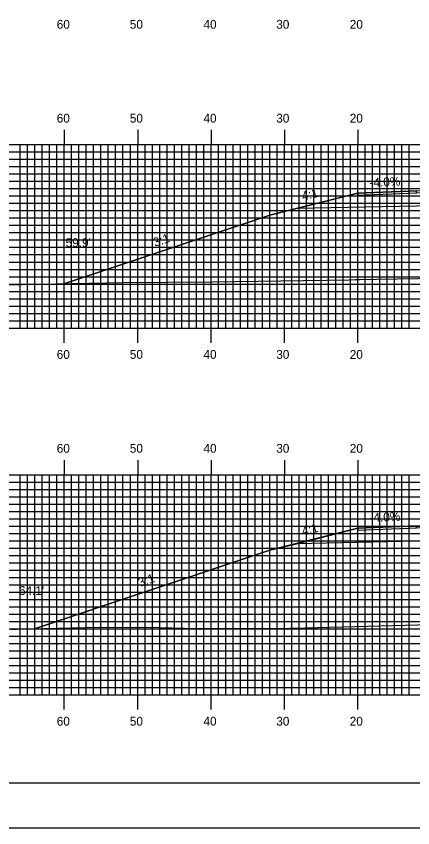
# Model space of a CAD drawing. Extents: x 1787763 to 1788106, y 442591 to 442811.
# Drawn here: x 1787862.1 to 1787916.1, y 442590.5 to 442701.2 of the extents above; entities that cross this region are included whole.
import ezdxf

# ---------------------------------------------------------------- set-up
doc = ezdxf.new("R2010")
doc.units = 0
for name, color, linetype in [('ANNOTATION', 7, 'Continuous'), ('BORDER', 7, 'Continuous'), ('D_Roadway_Centerline', 7, 'Continuous'), ('D_Roadway_Edge_Shoulder', 7, 'Continuous'), ('D_Roadway_SlopeLines', 7, 'Continuous'), ('D_Roadway_SubGrade', 7, 'Continuous'), ('D_Text_Standard', 7, 'Continuous'), ('H_V ANNOTATION', 7, 'Continuous'), ('MAJOR', 7, 'Continuous'), ('MINOR', 7, 'Continuous'), ('PLOT BOUNDARY', 7, 'Continuous'), ('S_Roadway_Centerline', 7, 'Continuous')]:
    doc.layers.add(name, color=color, linetype=linetype)

msp = doc.modelspace()

# ---------------------------------------------------------------- linework, layer by layer
at = {"layer": 'BORDER'}
msp.add_lwpolyline([(1787779.02, 442596.67), (1788099.02, 442596.67), (1788099.02, 442806.67), (1787779.02, 442806.67)], close=True, dxfattribs=at)
at = {"layer": 'D_Roadway_Centerline'}
for points in [[(1787868.67, 442664.72), (1787896.62, 442674.04), (1787900.25, 442674.95), (1787908.62, 442677.04), (1787916.62, 442677.36), (1787928.62, 442677.62), (1787940.62, 442677.89), (1787948.62, 442677.57), (1787956.98, 442675.48), (1787960.62, 442674.57), (1787989.3, 442665.01)], [(1787864.55, 442617.68), (1787896.62, 442628.37), (1787900.25, 442629.27), (1787908.62, 442631.37), (1787916.62, 442631.69), (1787928.62, 442631.95), (1787940.62, 442632.21), (1787948.62, 442631.89), (1787956.98, 442629.8), (1787960.62, 442628.89), (1787992.37, 442618.31)]]:
    msp.add_lwpolyline(points, dxfattribs=at)
at = {"layer": 'D_Roadway_Edge_Shoulder'}
for points in [[(1787916.62, 442677.36), (1787908.62, 442677.04), (1787908.62, 442676.79), (1787916.62, 442677.11)], [(1787916.62, 442631.69), (1787908.62, 442631.37), (1787908.62, 442631.12), (1787916.62, 442631.44)]]:
    msp.add_lwpolyline(points, close=True, dxfattribs=at)
at = {"layer": 'D_Roadway_SlopeLines'}
for points in [[(1787908.62, 442677.04), (1787896.62, 442674.04), (1787868.67, 442664.72)], [(1787908.62, 442631.37), (1787896.62, 442628.37), (1787864.55, 442617.68)]]:
    msp.add_lwpolyline(points, dxfattribs=at)
at = {"layer": 'D_Roadway_SubGrade'}
for points in [[(1787916.62, 442675.27), (1787900.25, 442674.95), (1787908.62, 442677.04), (1787908.62, 442676.79), (1787916.62, 442677.11), (1787928.62, 442677.37), (1787940.62, 442677.64), (1787948.62, 442677.32), (1787948.62, 442677.57), (1787956.98, 442675.48), (1787940.62, 442675.8), (1787928.62, 442675.54)], [(1787916.62, 442629.6), (1787900.25, 442629.27), (1787908.62, 442631.37), (1787908.62, 442631.12), (1787916.62, 442631.44), (1787928.62, 442631.7), (1787940.62, 442631.96), (1787948.62, 442631.64), (1787948.62, 442631.89), (1787956.98, 442629.8), (1787940.62, 442630.13), (1787928.62, 442629.87)]]:
    msp.add_lwpolyline(points, close=True, dxfattribs=at)
at = {"layer": 'MAJOR'}
for p, q in [((1787868.62, 442685.67), (1787868.62, 442683.67)), ((1787878.62, 442685.67), (1787878.62, 442683.67)), ((1787888.62, 442685.67), (1787888.62, 442683.67)), ((1787898.62, 442685.67), (1787898.62, 442683.67)), ((1787908.62, 442685.67), (1787908.62, 442683.67)), ((1787788.62, 442683.67), (1788068.62, 442683.67)), ((1787788.62, 442683.67), (1788068.62, 442683.67)), ((1787868.62, 442658.67), (1787868.62, 442683.67)), ((1787878.62, 442658.67), (1787878.62, 442683.67)), ((1787888.62, 442658.67), (1787888.62, 442683.67)), ((1787898.62, 442658.67), (1787898.62, 442683.67)), ((1787908.62, 442658.67), (1787908.62, 442683.67)), ((1787788.62, 442678.67), (1788068.62, 442678.67)), ((1787788.62, 442673.67), (1788068.62, 442673.67)), ((1787788.62, 442668.67), (1788068.62, 442668.67)), ((1787788.62, 442663.67), (1788068.62, 442663.67)), ((1787788.62, 442658.67), (1788068.62, 442658.67)), ((1787788.62, 442658.67), (1788068.62, 442658.67)), ((1787868.62, 442656.66), (1787868.62, 442658.67)), ((1787878.62, 442656.66), (1787878.62, 442658.67)), ((1787888.62, 442656.66), (1787888.62, 442658.67)), ((1787898.62, 442656.66), (1787898.62, 442658.67)), ((1787908.62, 442656.66), (1787908.62, 442658.67)), ((1787868.62, 442640.67), (1787868.62, 442638.67)), ((1787878.62, 442640.67), (1787878.62, 442638.67)), ((1787888.62, 442640.67), (1787888.62, 442638.67)), ((1787898.62, 442640.67), (1787898.62, 442638.67)), ((1787908.62, 442640.67), (1787908.62, 442638.67)), ((1787788.62, 442638.67), (1788068.62, 442638.67)), ((1787788.62, 442638.67), (1788068.62, 442638.67)), ((1787868.62, 442608.67), (1787868.62, 442638.67)), ((1787878.62, 442608.67), (1787878.62, 442638.67)), ((1787888.62, 442608.67), (1787888.62, 442638.67)), ((1787898.62, 442608.67), (1787898.62, 442638.67)), ((1787908.62, 442608.67), (1787908.62, 442638.67)), ((1787788.62, 442633.67), (1788068.62, 442633.67)), ((1787788.62, 442628.67), (1788068.62, 442628.67)), ((1787788.62, 442623.67), (1788068.62, 442623.67)), ((1787788.62, 442618.67), (1788068.62, 442618.67)), ((1787788.62, 442613.67), (1788068.62, 442613.67)), ((1787788.62, 442608.67), (1788068.62, 442608.67)), ((1787788.62, 442608.67), (1788068.62, 442608.67)), ((1787868.62, 442606.66), (1787868.62, 442608.67)), ((1787878.62, 442606.66), (1787878.62, 442608.67)), ((1787888.62, 442606.66), (1787888.62, 442608.67)), ((1787898.62, 442606.66), (1787898.62, 442608.67)), ((1787908.62, 442606.66), (1787908.62, 442608.67))]:
    msp.add_line(p, q, dxfattribs=at)
at = {"layer": 'MINOR'}
for p, q in [((1787862.62, 442658.67), (1787862.62, 442683.67)), ((1787863.62, 442658.67), (1787863.62, 442683.67)), ((1787864.62, 442658.67), (1787864.62, 442683.67)), ((1787865.62, 442658.67), (1787865.62, 442683.67)), ((1787866.62, 442658.67), (1787866.62, 442683.67)), ((1787867.62, 442658.67), (1787867.62, 442683.67)), ((1787869.62, 442658.67), (1787869.62, 442683.67)), ((1787870.62, 442658.67), (1787870.62, 442683.67)), ((1787871.62, 442658.67), (1787871.62, 442683.67)), ((1787872.62, 442658.67), (1787872.62, 442683.67)), ((1787873.62, 442658.67), (1787873.62, 442683.67)), ((1787874.62, 442658.67), (1787874.62, 442683.67)), ((1787875.62, 442658.67), (1787875.62, 442683.67)), ((1787876.62, 442658.67), (1787876.62, 442683.67)), ((1787877.62, 442658.67), (1787877.62, 442683.67)), ((1787879.62, 442658.67), (1787879.62, 442683.67)), ((1787880.62, 442658.67), (1787880.62, 442683.67)), ((1787881.62, 442658.67), (1787881.62, 442683.67)), ((1787882.62, 442658.67), (1787882.62, 442683.67)), ((1787883.62, 442658.67), (1787883.62, 442683.67)), ((1787884.62, 442658.67), (1787884.62, 442683.67)), ((1787885.62, 442658.67), (1787885.62, 442683.67)), ((1787886.62, 442658.67), (1787886.62, 442683.67)), ((1787887.62, 442658.67), (1787887.62, 442683.67)), ((1787889.62, 442658.67), (1787889.62, 442683.67)), ((1787890.62, 442658.67), (1787890.62, 442683.67)), ((1787891.62, 442658.67), (1787891.62, 442683.67)), ((1787892.62, 442658.67), (1787892.62, 442683.67)), ((1787893.62, 442658.67), (1787893.62, 442683.67)), ((1787894.62, 442658.67), (1787894.62, 442683.67)), ((1787895.62, 442658.67), (1787895.62, 442683.67)), ((1787896.62, 442658.67), (1787896.62, 442683.67)), ((1787897.62, 442658.67), (1787897.62, 442683.67)), ((1787899.62, 442658.67), (1787899.62, 442683.67)), ((1787900.62, 442658.67), (1787900.62, 442683.67)), ((1787901.62, 442658.67), (1787901.62, 442683.67)), ((1787902.62, 442658.67), (1787902.62, 442683.67)), ((1787903.62, 442658.67), (1787903.62, 442683.67)), ((1787904.62, 442658.67), (1787904.62, 442683.67)), ((1787905.62, 442658.67), (1787905.62, 442683.67)), ((1787906.62, 442658.67), (1787906.62, 442683.67)), ((1787907.62, 442658.67), (1787907.62, 442683.67)), ((1787909.62, 442658.67), (1787909.62, 442683.67)), ((1787910.62, 442658.67), (1787910.62, 442683.67)), ((1787911.62, 442658.67), (1787911.62, 442683.67)), ((1787912.62, 442658.67), (1787912.62, 442683.67)), ((1787913.62, 442658.67), (1787913.62, 442683.67)), ((1787914.62, 442658.67), (1787914.62, 442683.67)), ((1787915.62, 442658.67), (1787915.62, 442683.67)), ((1787788.62, 442682.67), (1788068.62, 442682.67)), ((1787788.62, 442681.67), (1788068.62, 442681.67)), ((1787788.62, 442680.67), (1788068.62, 442680.67)), ((1787788.62, 442679.67), (1788068.62, 442679.67)), ((1787788.62, 442677.67), (1788068.62, 442677.67)), ((1787788.62, 442676.67), (1788068.62, 442676.67)), ((1787788.62, 442675.67), (1788068.62, 442675.67)), ((1787788.62, 442674.67), (1788068.62, 442674.67)), ((1787788.62, 442672.67), (1788068.62, 442672.67)), ((1787788.62, 442671.67), (1788068.62, 442671.67)), ((1787788.62, 442670.67), (1788068.62, 442670.67)), ((1787788.62, 442669.67), (1788068.62, 442669.67)), ((1787788.62, 442667.67), (1788068.62, 442667.67)), ((1787788.62, 442666.67), (1788068.62, 442666.67)), ((1787788.62, 442665.67), (1788068.62, 442665.67)), ((1787788.62, 442664.67), (1788068.62, 442664.67)), ((1787788.62, 442662.67), (1788068.62, 442662.67)), ((1787788.62, 442661.67), (1788068.62, 442661.67)), ((1787788.62, 442660.67), (1788068.62, 442660.67)), ((1787788.62, 442659.67), (1788068.62, 442659.67)), ((1787862.62, 442608.67), (1787862.62, 442638.67)), ((1787863.62, 442608.67), (1787863.62, 442638.67)), ((1787864.62, 442608.67), (1787864.62, 442638.67)), ((1787865.62, 442608.67), (1787865.62, 442638.67)), ((1787866.62, 442608.67), (1787866.62, 442638.67)), ((1787867.62, 442608.67), (1787867.62, 442638.67)), ((1787869.62, 442608.67), (1787869.62, 442638.67)), ((1787870.62, 442608.67), (1787870.62, 442638.67)), ((1787871.62, 442608.67), (1787871.62, 442638.67)), ((1787872.62, 442608.67), (1787872.62, 442638.67)), ((1787873.62, 442608.67), (1787873.62, 442638.67)), ((1787874.62, 442608.67), (1787874.62, 442638.67)), ((1787875.62, 442608.67), (1787875.62, 442638.67)), ((1787876.62, 442608.67), (1787876.62, 442638.67)), ((1787877.62, 442608.67), (1787877.62, 442638.67)), ((1787879.62, 442608.67), (1787879.62, 442638.67)), ((1787880.62, 442608.67), (1787880.62, 442638.67)), ((1787881.62, 442608.67), (1787881.62, 442638.67)), ((1787882.62, 442608.67), (1787882.62, 442638.67)), ((1787883.62, 442608.67), (1787883.62, 442638.67)), ((1787884.62, 442608.67), (1787884.62, 442638.67)), ((1787885.62, 442608.67), (1787885.62, 442638.67)), ((1787886.62, 442608.67), (1787886.62, 442638.67)), ((1787887.62, 442608.67), (1787887.62, 442638.67)), ((1787889.62, 442608.67), (1787889.62, 442638.67)), ((1787890.62, 442608.67), (1787890.62, 442638.67)), ((1787891.62, 442608.67), (1787891.62, 442638.67)), ((1787892.62, 442608.67), (1787892.62, 442638.67)), ((1787893.62, 442608.67), (1787893.62, 442638.67)), ((1787894.62, 442608.67), (1787894.62, 442638.67)), ((1787895.62, 442608.67), (1787895.62, 442638.67)), ((1787896.62, 442608.67), (1787896.62, 442638.67)), ((1787897.62, 442608.67), (1787897.62, 442638.67)), ((1787899.62, 442608.67), (1787899.62, 442638.67)), ((1787900.62, 442608.67), (1787900.62, 442638.67)), ((1787901.62, 442608.67), (1787901.62, 442638.67)), ((1787902.62, 442608.67), (1787902.62, 442638.67)), ((1787903.62, 442608.67), (1787903.62, 442638.67)), ((1787904.62, 442608.67), (1787904.62, 442638.67)), ((1787905.62, 442608.67), (1787905.62, 442638.67)), ((1787906.62, 442608.67), (1787906.62, 442638.67)), ((1787907.62, 442608.67), (1787907.62, 442638.67)), ((1787909.62, 442608.67), (1787909.62, 442638.67)), ((1787910.62, 442608.67), (1787910.62, 442638.67)), ((1787911.62, 442608.67), (1787911.62, 442638.67)), ((1787912.62, 442608.67), (1787912.62, 442638.67)), ((1787913.62, 442608.67), (1787913.62, 442638.67)), ((1787914.62, 442608.67), (1787914.62, 442638.67)), ((1787915.62, 442608.67), (1787915.62, 442638.67)), ((1787788.62, 442637.67), (1788068.62, 442637.67)), ((1787788.62, 442636.67), (1788068.62, 442636.67)), ((1787788.62, 442635.67), (1788068.62, 442635.67)), ((1787788.62, 442634.67), (1788068.62, 442634.67)), ((1787788.62, 442632.67), (1788068.62, 442632.67)), ((1787788.62, 442631.67), (1788068.62, 442631.67)), ((1787788.62, 442630.67), (1788068.62, 442630.67)), ((1787788.62, 442629.67), (1788068.62, 442629.67)), ((1787788.62, 442627.67), (1788068.62, 442627.67)), ((1787788.62, 442626.67), (1788068.62, 442626.67)), ((1787788.62, 442625.67), (1788068.62, 442625.67)), ((1787788.62, 442624.67), (1788068.62, 442624.67)), ((1787788.62, 442622.67), (1788068.62, 442622.67)), ((1787788.62, 442621.67), (1788068.62, 442621.67)), ((1787788.62, 442620.67), (1788068.62, 442620.67)), ((1787788.62, 442619.67), (1788068.62, 442619.67)), ((1787788.62, 442617.67), (1788068.62, 442617.67)), ((1787788.62, 442616.67), (1788068.62, 442616.67)), ((1787788.62, 442615.67), (1788068.62, 442615.67)), ((1787788.62, 442614.67), (1788068.62, 442614.67)), ((1787788.62, 442612.67), (1788068.62, 442612.67)), ((1787788.62, 442611.67), (1788068.62, 442611.67)), ((1787788.62, 442610.67), (1788068.62, 442610.67)), ((1787788.62, 442609.67), (1788068.62, 442609.67))]:
    msp.add_line(p, q, dxfattribs=at)
at = {"layer": 'PLOT BOUNDARY'}
msp.add_lwpolyline([(1787762.83, 442590.55), (1788102.83, 442590.55), (1788102.83, 442810.55), (1787762.83, 442810.55)], close=True, dxfattribs=at)
at = {"layer": 'S_Roadway_Centerline'}
for points in [[(1787860.67, 442664.56), (1787869.64, 442664.74), (1787876.65, 442664.89), (1787888.8, 442664.98), (1787907.44, 442665.24), (1787908.3, 442665.27), (1787908.88, 442665.29), (1787911.24, 442665.32), (1787928.11, 442665.61), (1787932.16, 442665.63), (1787938.6, 442665.55), (1787947.5, 442665.51), (1787956.04, 442665.43), (1787966.92, 442665.24), (1787967.96, 442665.22), (1787969.65, 442665.19), (1787986.43, 442664.99), (1787991.8, 442665.02)], [(1787861.36, 442617.63), (1787862.19, 442617.62), (1787873.43, 442617.87), (1787881.58, 442617.84), (1787885, 442617.77), (1787890.61, 442617.73), (1787897.18, 442617.72), (1787901.39, 442617.82), (1787920.22, 442618.32), (1787920.45, 442618.32), (1787920.58, 442618.33), (1787932.67, 442618.51), (1787940.25, 442618.58), (1787951.87, 442618.49), (1787956.3, 442618.43), (1787959.3, 442618.37), (1787968.35, 442618.22), (1787979.19, 442618.18), (1787980.22, 442618.17), (1787981.81, 442618.19), (1787992.2, 442618.3)]]:
    msp.add_lwpolyline(points, dxfattribs=at)

# ---------------------------------------------------------------- texts
at = {"layer": 'ANNOTATION'}
for s, rotation, p in [('-4.0%', 2.2906, (1787910.25, 442677.91)), ('4:1', 14.0362, (1787901.15, 442676.03)), ('3:1', 18.4348, (1787880.98, 442669.73)), ('-4.0%', 2.2906, (1787910.25, 442632.23)), ('4:1', 14.0362, (1787901.15, 442630.36)), ('3:1', 18.4348, (1787878.92, 442623.37))]:
    msp.add_text(s, height=1.2, rotation=rotation, dxfattribs=at).set_placement(p)
at = {"layer": 'D_Text_Standard'}
for s, p in [("59.9'", (1787868.8, 442669.71)), ("64.1'", (1787862.44, 442622.28))]:
    msp.add_text(s, height=1.2, dxfattribs=at).set_placement(p)
at = {"layer": 'H_V ANNOTATION'}
for s, p in [('60', (1787867.59, 442699.47)), ('50', (1787877.55, 442699.47)), ('40', (1787887.59, 442699.47)), ('30', (1787897.51, 442699.47)), ('20', (1787907.53, 442699.47)), ('60', (1787867.59, 442686.67)), ('50', (1787877.55, 442686.67)), ('40', (1787887.59, 442686.67)), ('30', (1787897.51, 442686.67)), ('20', (1787907.53, 442686.67)), ('60', (1787867.59, 442654.47)), ('50', (1787877.55, 442654.47)), ('40', (1787887.59, 442654.47)), ('30', (1787897.51, 442654.47)), ('20', (1787907.53, 442654.47)), ('60', (1787867.59, 442641.67)), ('50', (1787877.55, 442641.67)), ('40', (1787887.59, 442641.67)), ('30', (1787897.51, 442641.67)), ('20', (1787907.53, 442641.67)), ('60', (1787867.59, 442604.47)), ('50', (1787877.55, 442604.47)), ('40', (1787887.59, 442604.47)), ('30', (1787897.51, 442604.47)), ('20', (1787907.53, 442604.47))]:
    msp.add_text(s, height=1.2, dxfattribs=at).set_placement(p)

doc.saveas('drawing.dxf')
